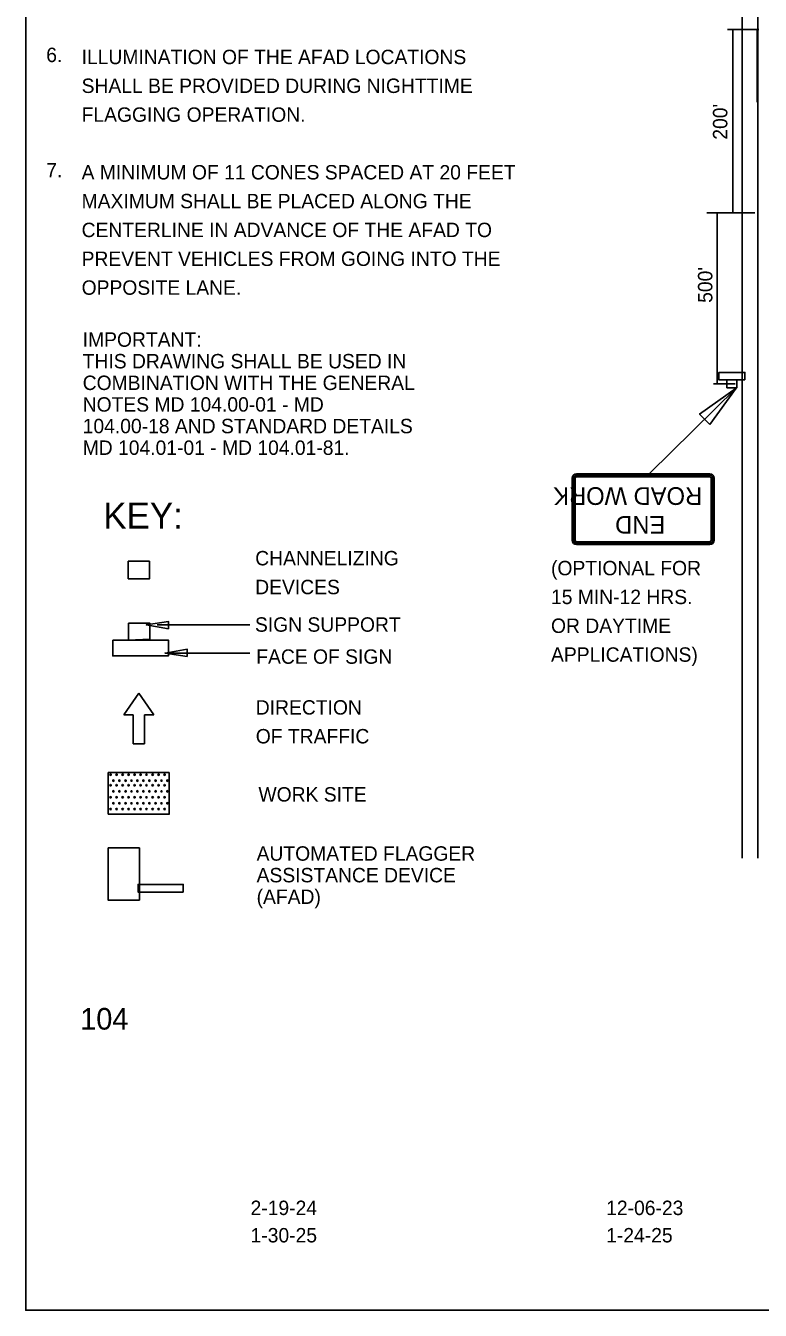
# Model space of a CAD drawing. Extents: x 21.7 to 29.1, y 5.9 to 16.2.
# Drawn here: x 21.72 to 24.78, y 5.86 to 11.2 of the extents above; entities that cross this region are included whole.
import ezdxf

# ---------------------------------------------------------------- set-up
doc = ezdxf.new("R2010")
doc.units = 0
for name, color, linetype in [('BORD-LINE', 7, 'Continuous'), ('C-SIGN-FACE-N', 7, 'Continuous'), ('DETL-DIMS', 7, 'Continuous'), ('DETL-LINE', 7, 'Continuous'), ('DETL-NOTE', 7, 'Continuous'), ('DETL-TITL', 7, 'Continuous'), ('TTLB-TEXT', 7, 'Continuous'), ('USER-BORD', 7, 'Continuous')]:
    doc.layers.add(name, color=color, linetype=linetype)

# ---------------------------------------------------------------- blocks, each defined once
blk = doc.blocks.new('SIGN')
at = {"layer": 'USER-BORD'}
for points in [[(-0.0013, 0.0018), (0.0011, 0.0019), (0.0011, 0.0037), (-0.0013, 0.0037)], [(-0.0031, 0.0018), (-0.0031, 0), (0.0032, 0), (0.0032, 0.0018)]]:
    blk.add_lwpolyline(points, close=True, dxfattribs=at)
blk = doc.blocks.new('DIR')
at = {"layer": 'USER-BORD'}
for p, q in [((0, 0.0001), (-0.0034, -0.0048)), ((0, 0.0001), (0.0034, -0.0048)), ((-0.0034, -0.0048), (-0.0013, -0.0048)), ((-0.0013, -0.0113), (-0.0013, -0.0048)), ((0.0034, -0.0048), (0.0013, -0.0048)), ((0.0013, -0.0113), (0.0013, -0.0048)), ((-0.0001, -0.0113), (-0.0013, -0.0113)), ((-0.0001, -0.0113), (0.0001, -0.0113)), ((0.0001, -0.0113), (0.0013, -0.0113))]:
    blk.add_line(p, q, dxfattribs=at)

msp = doc.modelspace()

# ---------------------------------------------------------------- linework, layer by layer
at = {"layer": 'BORD-LINE'}
msp.add_lwpolyline([(21.7194, 16.2106), (29.0936, 16.2106), (29.0936, 5.8575), (21.7194, 5.8575)], close=True, dxfattribs=at)
at = {"layer": 'C-SIGN-FACE-N'}
for p, q in [((23.993, 9.0628), (23.993, 9.3214)), ((23.999, 9.0628), (23.999, 9.3214)), ((24.0054, 9.0628), (24.0054, 9.3214)), ((24.0114, 9.3397), (24.5652, 9.3397)), ((24.0114, 9.3338), (24.5652, 9.3338)), ((24.0114, 9.3273), (24.5652, 9.3273)), ((24.5711, 9.3214), (24.5711, 9.0628)), ((24.5776, 9.3214), (24.5776, 9.0628)), ((24.5835, 9.3214), (24.5835, 9.0628)), ((24.5652, 9.0569), (24.0114, 9.0569)), ((24.5652, 9.0504), (24.0114, 9.0504)), ((24.5652, 9.0445), (24.0114, 9.0445)), ((24.5652, 9.0445), (24.0114, 9.0445))]:
    msp.add_line(p, q, dxfattribs=at)
for centre, radius, start, end in [((24.0115, 9.3213), 0.0185, 90, 180), ((24.0115, 9.3213), 0.0123, 90, 180), ((24.0115, 9.3213), 0.00615, 90, 180), ((24.5651, 9.3213), 0.0185, 360, 90), ((24.5651, 9.3213), 0.0123, 360, 90), ((24.5651, 9.3213), 0.00615, 360, 90), ((24.0115, 9.063), 0.0185, 180, 270), ((24.0115, 9.063), 0.0123, 180, 270), ((24.0115, 9.063), 0.00615, 180, 270), ((24.5651, 9.063), 0.0185, 270, 360), ((24.5651, 9.063), 0.0123, 270, 360), ((24.5651, 9.063), 0.00615, 270, 360)]:
    msp.add_arc(centre, radius, start, end, dxfattribs=at)
at = {"layer": 'DETL-DIMS'}
for p, q in [((24.639, 11.1888), (24.7694, 11.1888)), ((24.6614, 11.1888), (24.6614, 10.4252)), ((24.7635, 11.1888), (24.7635, 10.886)), ((24.7536, 10.4252), (24.553, 10.4252)), ((24.5965, 10.4252), (24.5965, 9.7141)), ((24.6761, 9.6954), (24.3158, 9.3421)), ((24.6713, 9.7141), (24.5805, 9.7141)), ((22.267, 8.7102), (22.6525, 8.7102)), ((22.2995, 8.5935), (22.6525, 8.5935))]:
    msp.add_line(p, q, dxfattribs=at)
for points in [[(24.566, 9.5445), (24.523, 9.5881), (24.6761, 9.6954)], [(22.313, 8.6946), (22.313, 8.725), (22.221, 8.7102)], [(22.3915, 8.5788), (22.3915, 8.6092), (22.2995, 8.5935)]]:
    msp.add_lwpolyline(points, close=True, dxfattribs=at)
at = {"layer": 'DETL-LINE'}
for p, q in [((24.7011, 9.2959), (24.7011, 15.5751)), ((24.7651, 9.2959), (24.7651, 15.5751)), ((24.6998, 7.7401), (24.6998, 9.2959)), ((24.7651, 7.7401), (24.7651, 9.2959)), ((22.317, 8.096), (22.063, 8.096)), ((22.317, 8.096), (22.063, 8.096)), ((22.317, 8.096), (22.063, 8.096)), ((22.317, 8.096), (22.063, 8.096)), ((22.0631, 7.922), (22.0631, 8.096)), ((22.0631, 7.922), (22.0631, 8.096)), ((22.0716, 8.0871), (22.0716, 8.0871)), ((22.0724, 8.0871), (22.0724, 8.0871)), ((22.0972, 8.0871), (22.0972, 8.0871)), ((22.0972, 8.0871), (22.0972, 8.0871)), ((22.122, 8.0871), (22.122, 8.0871)), ((22.1228, 8.0871), (22.1228, 8.0871)), ((22.1468, 8.0871), (22.1468, 8.0871)), ((22.1476, 8.0871), (22.1476, 8.0871)), ((22.1716, 8.0871), (22.1716, 8.0871)), ((22.1724, 8.0871), (22.1724, 8.0871)), ((22.1972, 8.0871), (22.1972, 8.0871)), ((22.1972, 8.0871), (22.1972, 8.0871)), ((22.222, 8.0871), (22.222, 8.0871)), ((22.222, 8.0871), (22.222, 8.0871)), ((22.2468, 8.0871), (22.2468, 8.0871)), ((22.2476, 8.0871), (22.2476, 8.0871)), ((22.2716, 8.0871), (22.2716, 8.0871)), ((22.2724, 8.0871), (22.2724, 8.0871)), ((22.2972, 8.0871), (22.2972, 8.0871)), ((22.2972, 8.0871), (22.2972, 8.0871)), ((22.317, 7.922), (22.317, 8.096)), ((22.317, 7.922), (22.317, 8.096)), ((22.317, 7.922), (22.317, 8.096)), ((22.317, 7.922), (22.317, 8.096)), ((22.0716, 8.0433), (22.0716, 8.0433)), ((22.0724, 8.0433), (22.0724, 8.0433)), ((22.0844, 8.0623), (22.0844, 8.0623)), ((22.0844, 8.0623), (22.0844, 8.0623)), ((22.0972, 8.0433), (22.0972, 8.0433)), ((22.0972, 8.0433), (22.0972, 8.0433)), ((22.1092, 8.0623), (22.1092, 8.0623)), ((22.1092, 8.0623), (22.1092, 8.0623)), ((22.122, 8.0433), (22.122, 8.0433)), ((22.1228, 8.0433), (22.1228, 8.0433)), ((22.1348, 8.0623), (22.1348, 8.0623)), ((22.1348, 8.0623), (22.1348, 8.0623)), ((22.1468, 8.0433), (22.1468, 8.0433)), ((22.1476, 8.0433), (22.1476, 8.0433)), ((22.1596, 8.0623), (22.1596, 8.0623)), ((22.1596, 8.0623), (22.1596, 8.0623)), ((22.1716, 8.0433), (22.1716, 8.0433)), ((22.1724, 8.0433), (22.1724, 8.0433)), ((22.1844, 8.0623), (22.1844, 8.0623)), ((22.1844, 8.0623), (22.1844, 8.0623)), ((22.1972, 8.0433), (22.1972, 8.0433)), ((22.1972, 8.0433), (22.1972, 8.0433)), ((22.2092, 8.0623), (22.2092, 8.0623)), ((22.2092, 8.0623), (22.2092, 8.0623)), ((22.222, 8.0433), (22.222, 8.0433)), ((22.222, 8.0433), (22.222, 8.0433)), ((22.234, 8.0623), (22.234, 8.0623)), ((22.234, 8.0623), (22.234, 8.0623)), ((22.2468, 8.0433), (22.2468, 8.0433)), ((22.2476, 8.0433), (22.2476, 8.0433)), ((22.2596, 8.0623), (22.2596, 8.0623)), ((22.2596, 8.0623), (22.2596, 8.0623)), ((22.2716, 8.0433), (22.2716, 8.0433)), ((22.2724, 8.0433), (22.2724, 8.0433)), ((22.2844, 8.0623), (22.2844, 8.0623)), ((22.2844, 8.0623), (22.2844, 8.0623)), ((22.2972, 8.0433), (22.2972, 8.0433)), ((22.2972, 8.0433), (22.2972, 8.0433)), ((22.3092, 8.0623), (22.3092, 8.0623)), ((22.3092, 8.0623), (22.3092, 8.0623)), ((22.0716, 7.9929), (22.0716, 7.9929)), ((22.0724, 7.9929), (22.0724, 7.9929)), ((22.0844, 8.0177), (22.0844, 8.0177)), ((22.0844, 7.9681), (22.0844, 7.9681)), ((22.0844, 7.9681), (22.0844, 7.9681)), ((22.0972, 7.9929), (22.0972, 7.9929)), ((22.0972, 7.9929), (22.0972, 7.9929)), ((22.1092, 8.0177), (22.1092, 8.0177)), ((22.1092, 7.9681), (22.1092, 7.9681)), ((22.1092, 7.9681), (22.1092, 7.9681)), ((22.122, 7.9929), (22.122, 7.9929)), ((22.1228, 7.9929), (22.1228, 7.9929)), ((22.1348, 8.0177), (22.1348, 8.0177)), ((22.1348, 7.9681), (22.1348, 7.9681)), ((22.1348, 7.9681), (22.1348, 7.9681)), ((22.1468, 7.9929), (22.1468, 7.9929)), ((22.1476, 7.9929), (22.1476, 7.9929)), ((22.1596, 8.0177), (22.1596, 8.0177)), ((22.1596, 7.9681), (22.1596, 7.9681)), ((22.1596, 7.9681), (22.1596, 7.9681)), ((22.1716, 7.9929), (22.1716, 7.9929)), ((22.1724, 7.9929), (22.1724, 7.9929)), ((22.1844, 8.0177), (22.1844, 8.0177)), ((22.1844, 7.9681), (22.1844, 7.9681)), ((22.1844, 7.9681), (22.1844, 7.9681)), ((22.1972, 7.9929), (22.1972, 7.9929)), ((22.1972, 7.9929), (22.1972, 7.9929)), ((22.2092, 8.0177), (22.2092, 8.0177)), ((22.2092, 7.9681), (22.2092, 7.9681)), ((22.2092, 7.9681), (22.2092, 7.9681)), ((22.222, 7.9929), (22.222, 7.9929)), ((22.222, 7.9929), (22.222, 7.9929)), ((22.234, 8.0177), (22.234, 8.0177)), ((22.234, 7.9681), (22.234, 7.9681)), ((22.234, 7.9681), (22.234, 7.9681)), ((22.2468, 7.9929), (22.2468, 7.9929)), ((22.2476, 7.9929), (22.2476, 7.9929)), ((22.2596, 8.0177), (22.2596, 8.0177)), ((22.2596, 7.9681), (22.2596, 7.9681)), ((22.2596, 7.9681), (22.2596, 7.9681)), ((22.2716, 7.9929), (22.2716, 7.9929)), ((22.2724, 7.9929), (22.2724, 7.9929)), ((22.2844, 8.0177), (22.2844, 8.0177)), ((22.2844, 7.9681), (22.2844, 7.9681)), ((22.2844, 7.9681), (22.2844, 7.9681)), ((22.2972, 7.9929), (22.2972, 7.9929)), ((22.2972, 7.9929), (22.2972, 7.9929)), ((22.3092, 8.0177), (22.3092, 8.0177)), ((22.3092, 7.9681), (22.3092, 7.9681)), ((22.3092, 7.9681), (22.3092, 7.9681)), ((22.0631, 7.922), (22.3171, 7.922)), ((22.0716, 7.9437), (22.0716, 7.9437)), ((22.0724, 7.9437), (22.0724, 7.9437)), ((22.0972, 7.9437), (22.0972, 7.9437)), ((22.0972, 7.9437), (22.0972, 7.9437)), ((22.122, 7.9437), (22.122, 7.9437)), ((22.1228, 7.9437), (22.1228, 7.9437)), ((22.1468, 7.9437), (22.1468, 7.9437)), ((22.1476, 7.9437), (22.1476, 7.9437)), ((22.1716, 7.9437), (22.1716, 7.9437)), ((22.1724, 7.9437), (22.1724, 7.9437)), ((22.1972, 7.9437), (22.1972, 7.9437)), ((22.1972, 7.9437), (22.1972, 7.9437)), ((22.222, 7.9437), (22.222, 7.9437)), ((22.222, 7.9437), (22.222, 7.9437)), ((22.2468, 7.9437), (22.2468, 7.9437)), ((22.2476, 7.9437), (22.2476, 7.9437)), ((22.2716, 7.9437), (22.2716, 7.9437)), ((22.2724, 7.9437), (22.2724, 7.9437)), ((22.2972, 7.9437), (22.2972, 7.9437)), ((22.2972, 7.9437), (22.2972, 7.9437))]:
    msp.add_line(p, q, dxfattribs=at)
for points in [[(24.7119, 9.7305), (24.7119, 9.7614), (24.6037, 9.7614), (24.6037, 9.7305)], [(24.6783, 9.7305), (24.637, 9.7305), (24.637, 9.6977), (24.6783, 9.6977)], [(22.1458, 8.9016), (22.1458, 8.9752), (22.2341, 8.9752), (22.2341, 8.9016)], [(22.1458, 8.9016), (22.1458, 8.9752), (22.2341, 8.9752), (22.2341, 8.9016)], [(22.1927, 7.5643), (22.1927, 7.7819), (22.0627, 7.7819), (22.0627, 7.5643)], [(22.375, 7.5985), (22.375, 7.6299), (22.1868, 7.6299), (22.1868, 7.5985)]]:
    msp.add_lwpolyline(points, close=True, dxfattribs=at)
for centre in [(22.0724, 8.087), (22.0972, 8.087), (22.1228, 8.087), (22.1476, 8.087), (22.1724, 8.087), (22.1972, 8.087), (22.222, 8.087), (22.2476, 8.087), (22.2724, 8.087), (22.2972, 8.087), (22.0724, 8.0433), (22.0844, 8.0622), (22.0972, 8.0433), (22.1092, 8.0622), (22.1228, 8.0433), (22.1348, 8.0622), (22.1476, 8.0433), (22.1596, 8.0622), (22.1724, 8.0433), (22.1844, 8.0622), (22.1972, 8.0433), (22.2092, 8.0622), (22.222, 8.0433), (22.234, 8.0622), (22.2476, 8.0433), (22.2596, 8.0622), (22.2724, 8.0433), (22.2844, 8.0622), (22.2972, 8.0433), (22.3092, 8.0622), (22.0724, 7.9929), (22.0844, 8.0177), (22.0844, 7.9681), (22.0972, 7.9929), (22.1092, 8.0177), (22.1092, 7.9681), (22.1228, 7.9929), (22.1348, 8.0177), (22.1348, 7.9681), (22.1476, 7.9929), (22.1596, 8.0177), (22.1596, 7.9681), (22.1724, 7.9929), (22.1844, 8.0177), (22.1844, 7.9681), (22.1972, 7.9929), (22.2092, 8.0177), (22.2092, 7.9681), (22.222, 7.9929), (22.234, 8.0177), (22.234, 7.9681), (22.2476, 7.9929), (22.2596, 8.0177), (22.2596, 7.9681), (22.2724, 7.9929), (22.2844, 8.0177), (22.2844, 7.9681), (22.2972, 7.9929), (22.3092, 8.0177), (22.3092, 7.9681), (22.0724, 7.9437), (22.0972, 7.9437), (22.1228, 7.9437), (22.1476, 7.9437), (22.1724, 7.9437), (22.1972, 7.9437), (22.222, 7.9437), (22.2476, 7.9437), (22.2724, 7.9437), (22.2972, 7.9437)]:
    msp.add_circle(centre, 0.00291, dxfattribs=at)

# ---------------------------------------------------------------- block references
for name, p, xscale, yscale in [('SIGN', (22.1955, 8.5813), 36.8, 36.8), ('DIR', (22.19, 8.424), 18.4, 18.4)]:
    msp.add_blockref(name, p, dxfattribs=dict(at, xscale=xscale, yscale=yscale))

# ---------------------------------------------------------------- texts
at = {"layer": 'C-SIGN-FACE-N'}
for s, p in [('ROAD WORK', (24.5339, 9.2837)), ('END', (24.3804, 9.1638))]:
    msp.add_text(s, height=0.07381, rotation=180, dxfattribs=at).set_placement(p)
at = {"layer": 'DETL-NOTE'}
for s, p in [('6.', (21.8048, 11.0532)), ('ILLUMINATION OF THE AFAD LOCATIONS ', (21.952, 11.0446)), ('SHALL BE PROVIDED DURING NIGHTTIME ', (21.952, 10.9246)), ('FLAGGING OPERATION.', (21.952, 10.8046)), ('7.', (21.8048, 10.5732)), ('A MINIMUM OF 11 CONES SPACED AT 20 FEET ', (21.952, 10.5646)), ('MAXIMUM SHALL BE PLACED ALONG THE ', (21.952, 10.4446)), ('CENTERLINE IN ADVANCE OF THE AFAD TO ', (21.952, 10.3246)), ('PREVENT VEHICLES FROM GOING INTO THE ', (21.952, 10.2046)), ('OPPOSITE LANE.', (21.952, 10.0846)), ('IMPORTANT:', (21.9565, 9.8682)), ('THIS DRAWING SHALL BE USED IN ', (21.9565, 9.7782)), ('COMBINATION WITH THE GENERAL ', (21.9565, 9.6882)), ('NOTES MD 104.00-01 - MD ', (21.9565, 9.5982)), ('104.00-18 AND STANDARD DETAILS ', (21.9565, 9.5082)), ('MD 104.01-01 - MD 104.01-81.', (21.9565, 9.4182)), ('CHANNELIZING', (22.6743, 8.9582)), ('(OPTIONAL FOR', (23.9051, 8.917)), ('DEVICES', (22.6743, 8.8382)), ('15 MIN-12 HRS. ', (23.9051, 8.797)), ('SIGN SUPPORT', (22.6733, 8.682)), ('OR DAYTIME', (23.9051, 8.677)), ('FACE OF SIGN', (22.6786, 8.5486)), ('APPLICATIONS)', (23.9051, 8.557)), ('DIRECTION', (22.6767, 8.3371)), ('OF TRAFFIC', (22.6767, 8.2171)), ('WORK SITE', (22.6878, 7.9751)), ('AUTOMATED FLAGGER ', (22.6801, 7.7289)), ('ASSISTANCE DEVICE ', (22.6801, 7.6389)), ('(AFAD) ', (22.6801, 7.5489))]:
    msp.add_text(s, height=0.06, dxfattribs=at).set_placement(p)
for s, p in [("200'", (24.6388, 10.7302)), ("500'", (24.5764, 10.0511))]:
    msp.add_text(s, height=0.06, rotation=90, dxfattribs=at).set_placement(p)
at = {"layer": 'DETL-TITL'}
msp.add_text('KEY:', height=0.10852, dxfattribs=at).set_placement((22.0424, 9.111))
at = {"layer": 'TTLB-TEXT'}
for s, height, p in [('104', 0.09, (21.9461, 7.0259)), ('2-19-24', 0.06, (22.655, 6.2539)), ('12-06-23', 0.06, (24.1346, 6.2539)), ('1-30-25', 0.06, (22.655, 6.14)), ('1-24-25', 0.06, (24.1346, 6.14))]:
    msp.add_text(s, height=height, dxfattribs=at).set_placement(p)

doc.saveas('drawing.dxf')
